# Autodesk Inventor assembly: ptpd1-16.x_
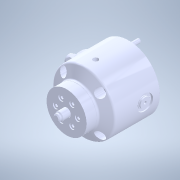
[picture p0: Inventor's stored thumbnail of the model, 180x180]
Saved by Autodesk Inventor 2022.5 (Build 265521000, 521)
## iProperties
Created: 2023-04
Part Number: ptpd1-16.x_
Document SubType Name: Assembly
Designer: ImaoCorp
Sending System: SOLIDWORKS 2021-2021301
MC: AMD64
MC_MODEL: Intel64 Family 6 Model 60 Stepping 3, GenuineIntel
OS: Windows_NT
FRU: Parasolid Version 32.1, build 255,  1- 1-2021
FORMAT: text
GUISE: transmit
KEY: ptpd1-16
FILE: ptpd1-16.x_t
DATE: Fri Apr  7 10:54:34 2023
Author: ImaoCorp
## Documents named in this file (5)
- X:\14_SW2022-Inv2022\00_全2023-1023新製品(TCC)まで\p\ptpd1-16\PTPD1-16.iam
- X:\14_SW2022-Inv2022\00_全2023-1023新製品(TCC)まで\p\ptpd1-16\ptpd1-16_01.ipt
- X:\14_SW2022-Inv2022\00_全2023-1023新製品(TCC)まで\p\ptpd1-16\ptpd1-16_02.ipt
- X:\14_SW2022-Inv2022\00_全2023-1023新製品(TCC)まで\p\ptpd1-16\ptpd1-16_03.ipt
- X:\14_SW2022-Inv2022\00_全2023-1023新製品(TCC)まで\p\ptpd1-16\ptpd1-16_04.ipt
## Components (4 placed, 4 different names)
1. ptpd1-16_01
2. ptpd1-16_02
3. ptpd1-16_03
4. ptpd1-16_04
